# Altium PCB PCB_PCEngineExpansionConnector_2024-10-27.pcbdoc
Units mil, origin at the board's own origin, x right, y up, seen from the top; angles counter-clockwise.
Board outline 3350 x 1945 mil, 2 copper layers (Top Layer, Bottom Layer); 6 components, 13 nets, 83 pads, 0 vias.
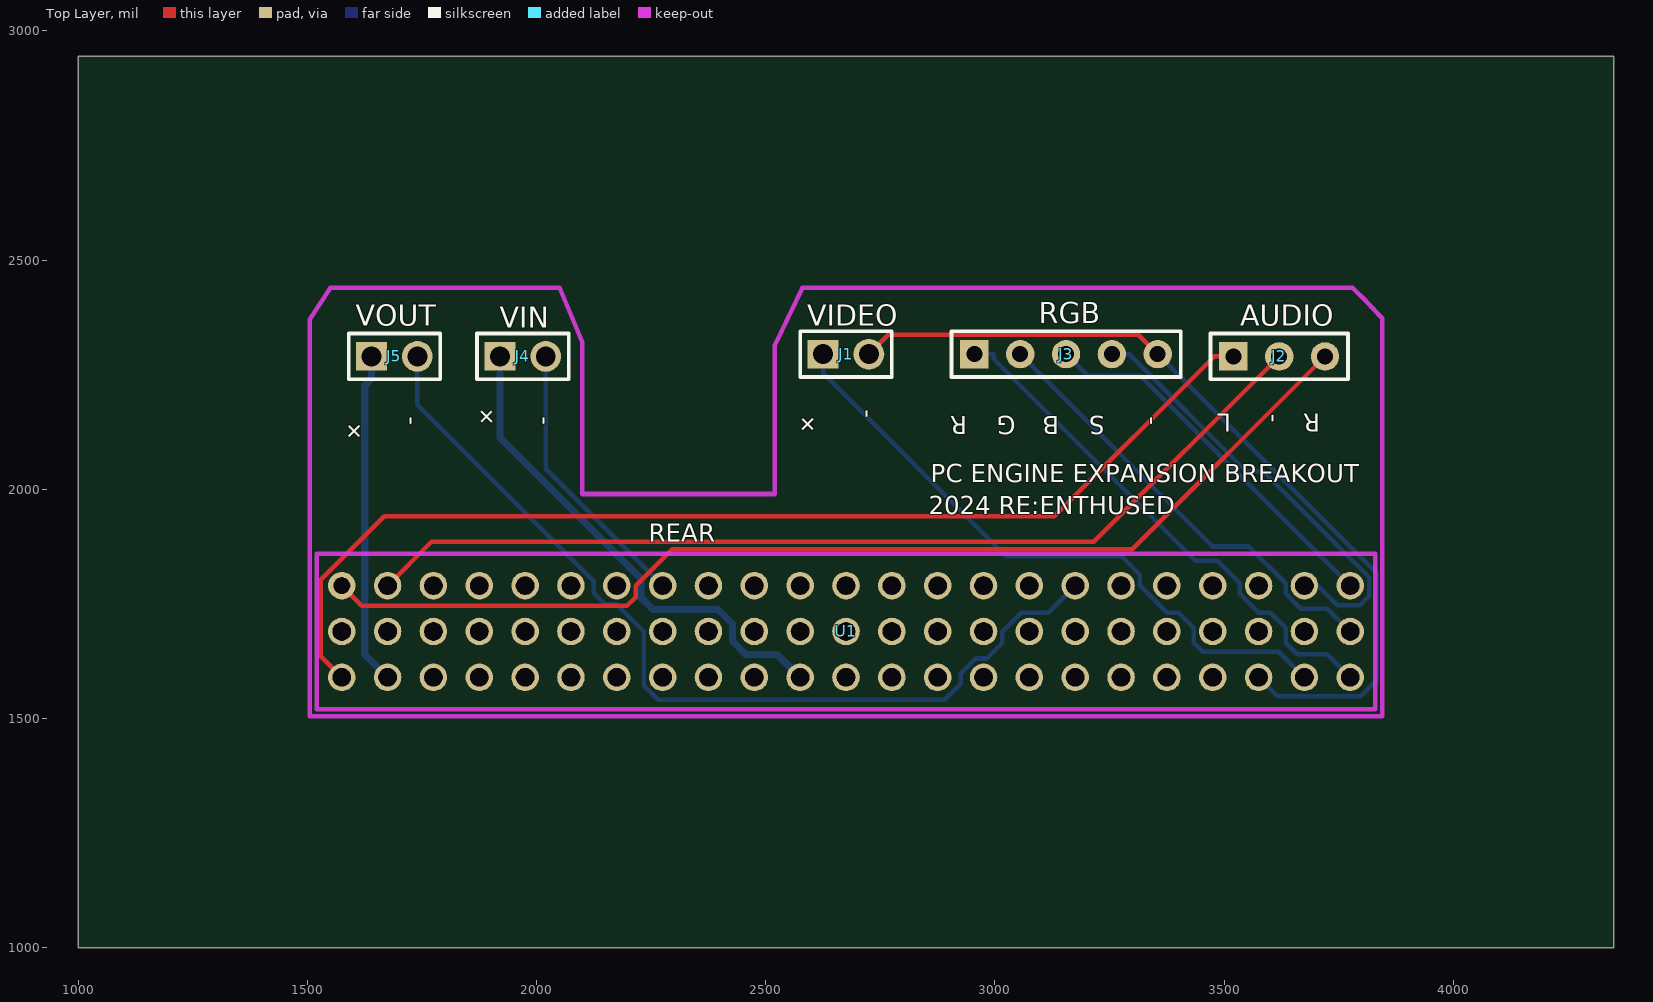
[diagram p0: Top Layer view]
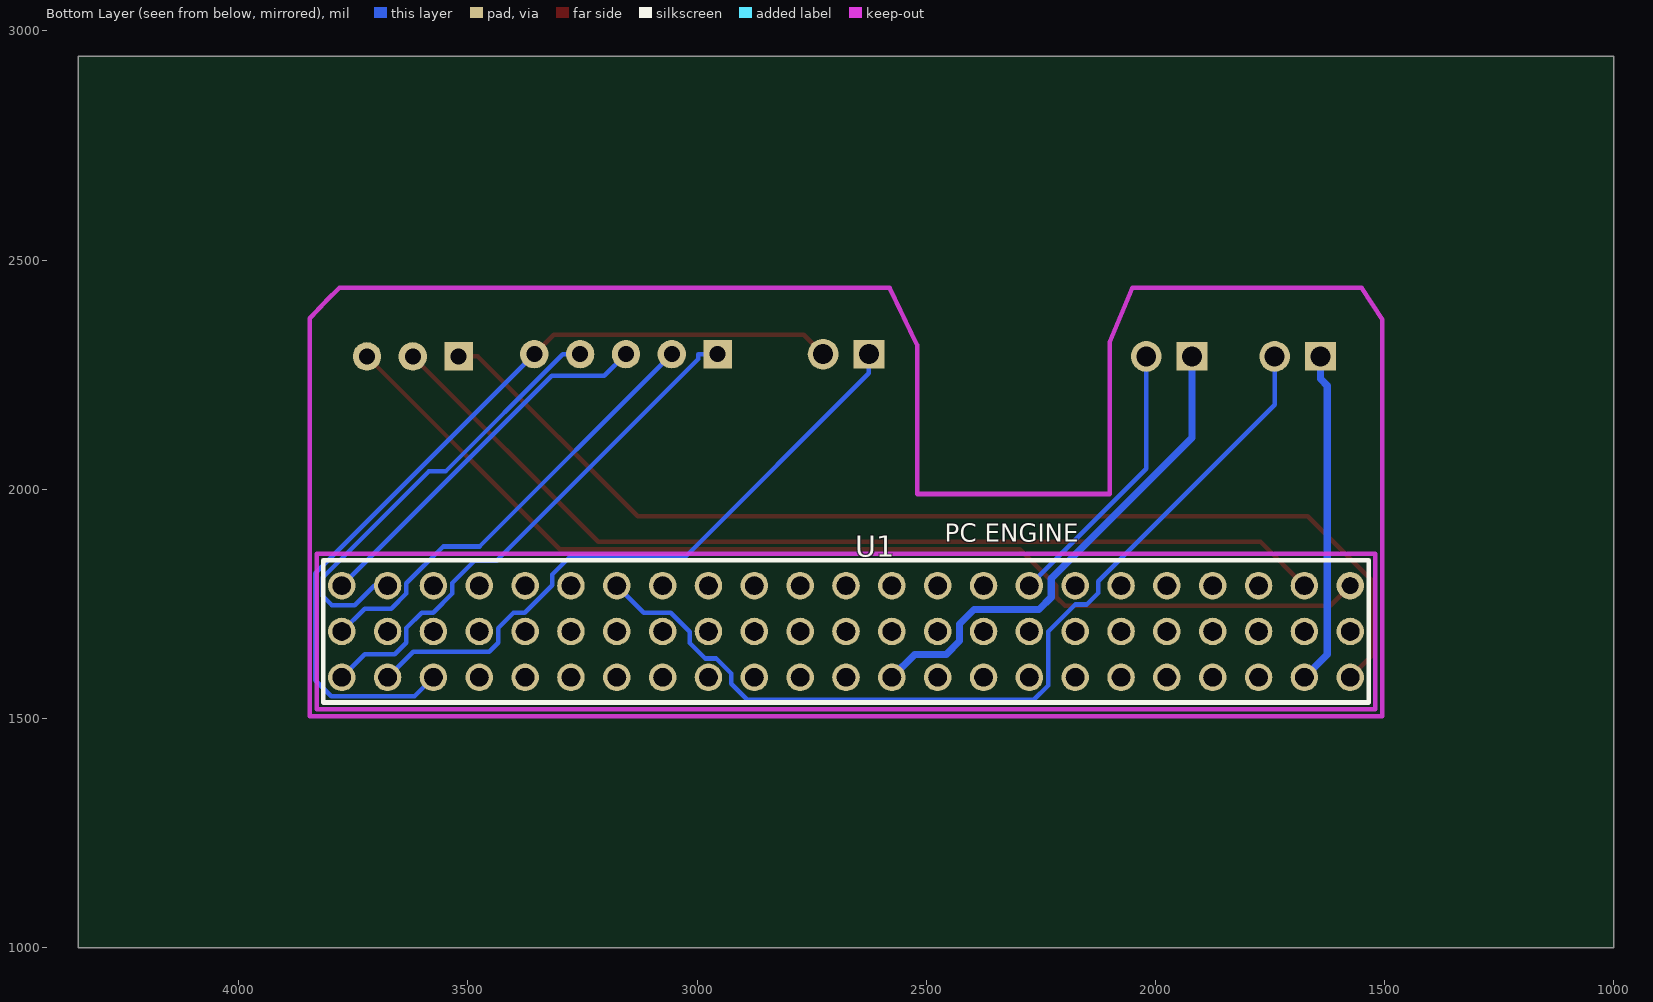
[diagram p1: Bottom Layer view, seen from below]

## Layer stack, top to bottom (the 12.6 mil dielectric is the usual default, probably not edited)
Top Layer: signal copper (thickness not stored)
Dielectric: dielectric 12.6, FR-4, Dk 4.8
Bottom Layer: signal copper (thickness not stored)

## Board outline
4350,1000 1000,1000 1000,2945 4350,2945

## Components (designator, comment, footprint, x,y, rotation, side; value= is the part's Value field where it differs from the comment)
J1 "VIDEO" HDR-M-2.54_1X2 2675,2295 r0 top
J2 "AUDIO" HDR-M-2.54_1X3 3620,2290 r0 top
J3 "RGB" HDR-M-2.54_1X5 3155,2295 r0 top
J4 "VIN" HDR-M-2.54_1X2 1970,2290 r0 top
J5 "VOUT" HDR-M-2.54_1X2 1690,2290 r0 top
U1 "PC ENGINE EXPANSION" "PC ENGINE EXPANSION" 2675,1690 r0 top

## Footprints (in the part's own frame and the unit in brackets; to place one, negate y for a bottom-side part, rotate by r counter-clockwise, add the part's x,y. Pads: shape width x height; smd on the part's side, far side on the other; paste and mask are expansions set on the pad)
HDR-M-2.54_1X2 [mm]
  rect 1.7x1.575 hole 1.1 paste+0 mask+0.051: 1(-1.27,0)
  round 1.7 hole 1.1 paste+0 mask+0.051: 2(1.27,0)
  silkscreen extent -2.54,-1.27 2.54,1.27
HDR-M-2.54_1X3 [mil]
  rect 62x62 hole 35 paste+0 mask+2: 1(-100,0)
  round 62 hole 35 paste+0 mask+2: 2(0,0) 3(100,0)
  silkscreen extent -150,-50 150,50
HDR-M-2.54_1X5 [mil]
  rect 62x62 hole 35 paste+0 mask+2: 1(-200,0)
  round 62 hole 35 paste+0 mask+2: 2(-100,0) 3(0,0) 4(100,0) 5(200,0)
  silkscreen extent -250,-50 250,50
"PC ENGINE EXPANSION" [mil]
  round 60 hole 40 slot 40.2 at 0 deg paste+0 mask+4: A0(0,0) A1(100,100) A2(100,0) A3(200,100) A4(300,100) A5(300,0) A6(400,100) A7(400,0) A8(-600,0) A9(-600,-100) A10(-500,-100) A11(-500,100) A12(500,0) A13(-600,100) A14(-700,-100) A15(600,100) A16(600,0) A17(-700,100) A18(-800,-100) A19(700,100) A20(700,0) Blue(1100,100) CDD(-1000,0) CEK(-800,100) CS(-900,-100) D0(-400,0) D1(-400,-100) D2(-300,100) D3(-300,0) D4(-200,100) D5(-200,0) D6(-100,100) D7(0,100) DCK(-300,-100) GND(-1000,100) GNDb(-400,100) GNDc(500,100) GNDd(800,100) GNDe(900,-100) GREEN(1100,0) HSM(-900,0) HSn(-100,0) HUD(-900,100) IRQ2(900,0) LEFT(-1100,-100) RDY(800,0) RED(1100,-100) RST(1000,0) SNDin(-1100,0) SPBG(0,-100) Sync(1000,100) VD0(800,-100) VD1(700,-100) VD2(600,-100) VD3(500,-100) VD4(400,-100) VD5(300,-100) VD6(200,0) VD7(100,-100) VID(1000,-100) Vin(-100,-100) Vin2(200,-100) Vout(-1000,-100) Vout2(900,100) VSn(-200,-100) WR(-800,0) XNMI(-700,0) XRD(-500,0)
  round 60 hole 36 slot 36.2 at 0 deg paste+0 mask+4: RIGHT(-1100,100)
  Keep-Out Layer lines w10: -1155,-170 1155,-170 1155,170 -1141.7,170 -1155,170 -1155,157.5 -1155,-170

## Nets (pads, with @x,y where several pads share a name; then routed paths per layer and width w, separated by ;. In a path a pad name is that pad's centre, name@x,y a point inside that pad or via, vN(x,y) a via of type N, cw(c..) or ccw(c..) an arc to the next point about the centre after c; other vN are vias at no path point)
AUDIOG: J2.2 U1.GND | length 2152.1
  Top Layer w10: U1.GND 1770.8,1885.8 3215.8,1885.8 J2.2
AUDIOL: J2.1 U1.LEFT | length 2423.9
  Top Layer w10: U1.LEFT 1529.38,1635.62 1529.38,1802.45 1668.02,1941.09 3129.1,1941.09 3478.01,2290 J2.1
AUDIOR: J2.3 U1.RIGHT | length 2403
  Top Layer w10: U1.RIGHT 1618.75,1746.25 2197.31,1746.25 2216.06,1765 2216.06,1790.02 2295.78,1869.74 3299.74,1869.74 J2.3
BLUE: J3.3 U1.Blue | length 829.2
  Bottom Layer w10: J3.3 3202.06,2247.94 3317.06,2247.94 U1.Blue
COMP: J1.1 U1.VID | length 1399.3
  Bottom Layer w10: J1.1 2625,2253.01 3024.32,1853.69 3276.64,1853.69 3316.06,1814.27 3316.06,1790.7 3375.7,1731.06 3400.36,1731.06 3433.94,1697.48 3433.94,1665.25 3453.52,1645.67 3619.33,1645.67 U1.VID
GREEN: J3.2 U1.GREEN | length 983.8
  Bottom Layer w10: J3.2 3474.53,1875.47 3553.83,1875.47 3633.94,1795.36 3633.94,1772.78 3666.72,1740 3725,1740 U1.GREEN
RED: J3.1 U1.RED | length 1150.4
  Bottom Layer w10: J3.1 2996.99,2295 2996.99,2284.5 3436.74,1844.75 3484.89,1844.75 3533.94,1795.7 3533.94,1772.86 3575.74,1731.06 3600.38,1731.06 3633.94,1697.5 3633.94,1665.25 3659.19,1640 3725,1640 U1.RED
SYNC: J3.4 U1.Sync | length 971
  Bottom Layer w10: J3.4 3292.72,2295 3548.61,2039.11 3585.6,2039.11 3816.07,1808.64 3816.07,1767.05 3796.43,1747.41 3747.01,1747.41 3704.42,1790 U1.Sync
VGND: J1.2 J3.5 U1.GNDe | length 1863.6
  Top Layer w10: J1.2 2767.06,2337.06 3312.94,2337.06 J3.5
  Bottom Layer w10: J3.5 3832.94,1817.06 3832.94,1583.95 3797.56,1548.57 3616.43,1548.57 U1.GNDe
VIN: J4.1 U1.Vin | length 1094.4
  Bottom Layer w15.75: J4.1 1920,2112.85 2227.27,1805.58 2227.27,1764.59 2254.13,1737.73 2395.8,1737.73 2427.27,1706.26 2427.27,1669.21 2456.48,1640 2525,1640 U1.Vin
VING: J4.2 U1.GNDb | length 605.6
  Bottom Layer w10: J4.2 2020,2045 U1.GNDb
VOUT: J5.1 U1.Vout | length 726.9
  Bottom Layer w15.75: J5.1 1640,2241.28 1625,2226.28 1625,1640 U1.Vout
VOUTG: J5.2 U1.GNDc | length 2022
  Bottom Layer w10: J5.2 1740,2184.62 2125,1799.62 2125,1773.94 2150,1748.94 2175.01,1748.94 2233.94,1690.01 2233.94,1572.17 2265.17,1540.94 2890.01,1540.94 2925.01,1575.94 2925.01,1598.36 2957.71,1631.06 2982.24,1631.06 3016.06,1664.88 3016.06,1689.77 3057.35,1731.06 3116.06,1731.06 U1.GNDc
pads on no net: U1.A0 U1.A1 U1.A2 U1.A3 U1.A4 U1.A5 U1.A6 U1.A7 U1.A8 U1.A9 U1.A10 U1.A11 U1.A12 U1.A13 U1.A14 U1.A15 U1.A16 U1.A17 U1.A18 U1.A19 U1.A20 U1.CDD U1.CEK U1.CS U1.D0 U1.D1 U1.D2 U1.D3 U1.D4 U1.D5 U1.D6 U1.D7 U1.DCK U1.GNDd U1.HSM U1.HSn U1.HUD U1.IRQ2 U1.RDY U1.RST U1.SNDin U1.SPBG U1.VD0 U1.VD1 U1.VD2 U1.VD3 U1.VD4 U1.VD5 U1.VD6 U1.VD7 U1.Vin2 U1.Vout2 U1.VSn U1.WR U1.XNMI U1.XRD

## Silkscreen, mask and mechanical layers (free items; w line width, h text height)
Top Overlay:
  text "+" at 2596.08,2168.92 h39.37 r225
  text "L" at 3515,2164.68 h39.37 r180
  text "R" at 3710,2164.68 h39.37 r180
  text "R" at 2940,2159.68 h39.37 r180
  text "G" at 3045,2159.68 h39.37 r180
  text "B" at 3140,2159.68 h39.37 r180
  text "S" at 3240,2159.68 h39.37 r180
  text "-" at 2734.68,2155 h39.37 r90
  text "+" at 1606.08,2153.92 h39.37 r225
  text "+" at 1918.92,2153.92 h39.37 r135
  text "-" at 3619.68,2145 h39.37 r90
  text "-" at 1739.68,2140 h39.37 r90
  text "-" at 2029.68,2140 h39.37 r90
  text "-" at 3354.68,2140 h39.37 r90
  text "PC ENGINE EXPANSION BREAKOUT" at 2860,2015.32 h39.37
  text "2024 RE:ENTHUSED" at 2855,1945.32 h39.37
  text "REAR" at 2245,1885.32 h39.37
Bottom Overlay:
  text "PC ENGINE" at 2460,1885.32 h39.37
Document:
  lines w0.1: 2674.99,1972.49 2675.01,1972.51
